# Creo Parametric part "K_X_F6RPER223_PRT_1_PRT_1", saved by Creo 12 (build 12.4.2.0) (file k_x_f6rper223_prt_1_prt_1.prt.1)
Units: Custom; MM, KILOGRAM, SECS

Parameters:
  PTC_WM_ITERATION = "0"
  PTC_WM_VERSION = "-.0"
  PTC_WM_LIFECYCLE_STATE = "In Work"
  PTC_WM_LIFECYCLE = "MO_CADDocument"
  PTC_WM_CREATED_BY = "Maximilian Roepper (Z0017RMS: MO)"
  PTC_WM_CREATED_ON = "18-Sep-26 11:36:42 AM"
  PTC_WM_MODIFIED_BY = "Maximilian Roepper (Z0017RMS: MO)"
  PTC_WM_MODIFIED_ON = "18-Sep-26 11:36:46 AM"
  PDMLINKNUMBER = "PDM000071455307"
  PTC_WM_NAME = "k_x_f6rper223_prt_1_prt_1.prt"
  PTC_WM_NUMBER = "PDM000071455307"

Other parameters: WEIGHT, WEIGHT_FACTOR, WEIGHT_ADD, _MASS_TEMP, _DIFF_TEMP, MC_ERRORS, SUPPLIER

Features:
  1. coordinate system
  2. datum plane "PRT_YZ"
  3. datum plane "PRT_XY"
  4. datum plane "PRT_XZ"
  5. coordinate system
  6. datum axis
  7. datum axis
  8. datum axis
  9. coordinate system
  10. imported feature
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
Other named items: PRT, SIEMENS_MO, DRW_VIEW_ORG, PRT_X, PRT_Y, PRT_Z, CS0, ROUGH_GROB

Layers: 00_STD_CSYS-KSYS, 01_STD_PLANES-EBENEN, 02_STD_AXES-ACHSEN, 03_STD_CSYS-KSYS, 24_IMPORT_FEAT-IMPORT_KE

Surfaces: 18 tabulated cylinder, 6 plane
